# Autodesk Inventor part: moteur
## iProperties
Author: Administrateur
Created: 2001-04
Part Number: moteur
Material: Par défaut
Document SubType Name: Modélisation
Designer: Administrateur
Control State: 0
Master: False
Checked Out: False
PropertySet Name: Design Tracking Control
Shininess: 66.0
PropertySet Name: _Private Model Information
Length Units: 11269
Angle Units: 11283
Time Units: 11279
Mass Units: 11290
Length Display Precision: 3
Angle Display Precision: 2
Compacted: False
Density: 0.0
Volumn: 0.0
Area: 0.0
PropertySet Name: Model Information
